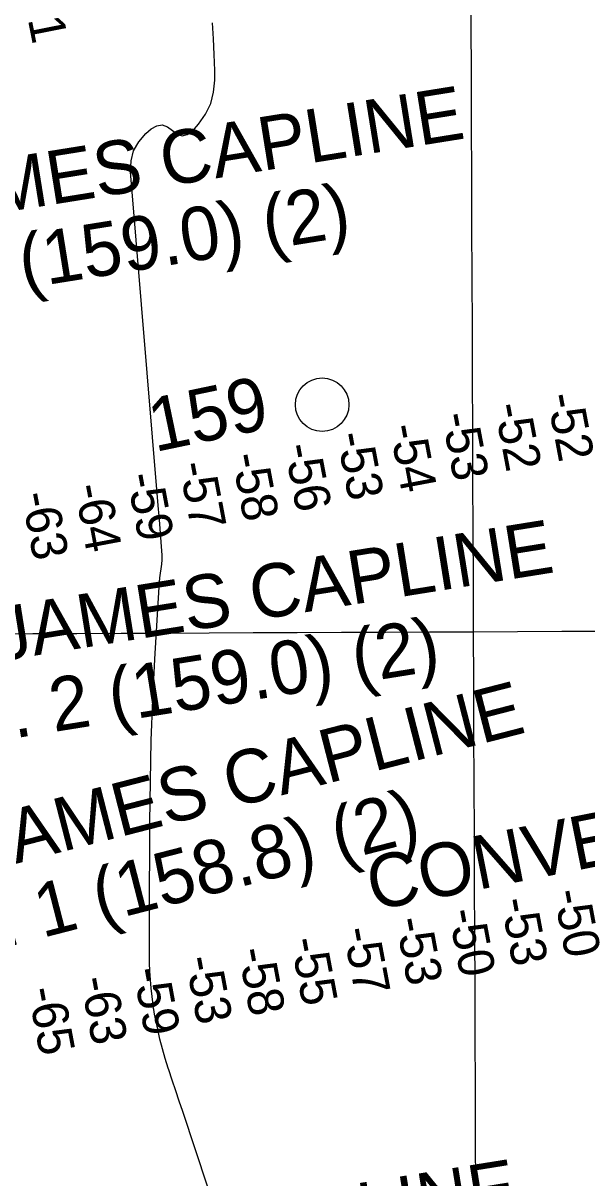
# Model space of a CAD drawing. Extents: x 3419139 to 3457078, y 540382 to 565875.
# Drawn here: x 3438230 to 3439284, y 550877 to 553037 of the extents above; entities that cross this region are included whole.
import ezdxf

# ---------------------------------------------------------------- set-up
doc = ezdxf.new("R2010")
doc.units = 0
for name, color, linetype in [('V-CHAN-NAID', 7, 'Continuous'), ('V-GRID-MAJR', 7, 'Continuous'), ('V-RIVR-IDEN', 7, 'Continuous'), ('V-RIVR-MILE', 7, 'Continuous'), ('V-RIVR-RANG', 7, 'Continuous'), ('V-TOPO-GNAM-IDEN', 7, 'Continuous'), ('V-TOPO-MINR', 7, 'Continuous')]:
    doc.layers.add(name, color=color, linetype=linetype)

msp = doc.modelspace()

# ---------------------------------------------------------------- linework, layer by layer
at = {"layer": 'V-GRID-MAJR'}
for points in [[(3439098.8, 545841.1), (3439072.3, 551898.7), (3439045.9, 557959.6), (3439019.4, 564020.6), (3439019.4, 564024.1)], [(3423248.5, 551833.1), (3428523.1, 551854.2), (3433797.7, 551876), (3439072.3, 551898.7), (3444346.9, 551922.1), (3449621.5, 551946.2), (3454896.1, 551971.2)]]:
    msp.add_spline(points, degree=3, dxfattribs=at)
at = {"layer": 'V-RIVR-MILE'}
msp.add_circle((3438789.1, 552323.2), 50, dxfattribs=at)
at = {"layer": 'V-TOPO-MINR'}
msp.add_lwpolyline([(3438575.5, 550860), (3438528.4, 551001.1), (3438521.9, 551020.6), (3438515.4, 551040.2), (3438508.9, 551059.7), (3438502.4, 551079.2), (3438501.4, 551082.4), (3438495.7, 551100.4), (3438490.5, 551118.5), (3438485.8, 551136.8), (3438481.6, 551155.2), (3438475.6, 551183.2), (3438474.7, 551187.7), (3438474, 551192.2), (3438473.3, 551196.6), (3438472.8, 551201.1), (3438469.5, 551232), (3438468.1, 551247.9), (3438467.1, 551263.8), (3438466.5, 551279.7), (3438466.3, 551295.7), (3438466.3, 551311.7), (3438466.4, 551327.6), (3438466.4, 551343.6), (3438466.5, 551359.6), (3438467, 551542.8), (3438467.9, 551619.1), (3438469.6, 551695.2), (3438472.6, 551771.4), (3438476.4, 551847.5), (3438484.2, 551982.8), (3438484.9, 551991.3), (3438485.7, 551999.7), (3438486.8, 552008.1), (3438488, 552016.4), (3438489.1, 552024.8), (3438489.8, 552033.2), (3438489.8, 552041.6), (3438489.5, 552050), (3438484.9, 552108.1), (3438484.3, 552114.7), (3438483.8, 552121.4), (3438483.2, 552128), (3438482.7, 552134.6), (3438430.7, 552758.8), (3438431.9, 552779), (3438436.5, 552797.9), (3438446.1, 552814.8), (3438459.1, 552830.4), (3438469.1, 552839.4), (3438479.7, 552844.6), (3438489.9, 552846.3), (3438499.6, 552842.8), (3438509, 552835.7), (3438518.2, 552829.3), (3438527.4, 552826.3), (3438536.9, 552828.7), (3438546.4, 552834.6), (3438557.9, 552847.8), (3438570.8, 552866.4), (3438580.7, 552886.2), (3438586, 552907.7), (3438588.3, 552930.2), (3438588.1, 552948.4), (3438587.4, 552978), (3438586.1, 553007.6), (3438583.8, 553037.1)], dxfattribs=at)

# ---------------------------------------------------------------- texts
at = {"layer": 'V-CHAN-NAID'}
for s, rotation, p in [('ST JAMES CAPLINE', 9.1127, (3437812, 552621.5)), ('NO. 2 (159.0) (2)', 9.1127, (3437848.7, 552478.9)), ('ST JAMES CAPLINE', 9.1127, (3437979.1, 551810.1)), ('NO. 2 (159.0) (2)', 9.1127, (3438015.8, 551667.5)), ('ST JAMES CAPLINE', 14.4384, (3437949.8, 551395.9)), ('NO. 1 (158.8) (2)', 14.4384, (3437999.6, 551257.3)), ('ST JAMES CAPLINE', 9.1127, (3437911, 550614.3))]:
    msp.add_text(s, height=100, rotation=rotation, dxfattribs=at).set_placement(p)
at = {"layer": 'V-RIVR-IDEN'}
msp.add_text('159', height=100, rotation=11.8277, dxfattribs=at).set_placement((3438476, 552234.4))
at = {"layer": 'V-RIVR-RANG'}
for s, rotation, p in [('-61', 281.16, (3438223.1, 553122.5)), ('-52', 280.6887, (3439208.9, 552340.4)), ('-53', 280.6887, (3439012.2, 552304.3)), ('-52', 280.6887, (3439110.6, 552322.1)), ('-54', 280.6887, (3438914.5, 552282.7)), ('-53', 280.6887, (3438815.6, 552267.7)), ('-56', 280.6887, (3438717.9, 552246.3)), ('-58', 280.6887, (3438619.5, 552228.5)), ('-57', 280.6887, (3438520.8, 552212.3)), ('-59', 280.6887, (3438423, 552191.2)), ('-63', 280.6887, (3438226.1, 552155.8)), ('-64', 280.6887, (3438325.1, 552170.8)), ('-53', 280.6027, (3439122.7, 551396.9)), ('-50', 280.6027, (3439221.5, 551412.7)), ('-50', 280.6027, (3439024.8, 551376.4)), ('-53', 280.6027, (3438926, 551360.6)), ('-57', 280.6027, (3438827.8, 551341.9)), ('-55', 280.6027, (3438729.6, 551322.7)), ('-58', 280.6027, (3438631.5, 551303.5)), ('-53', 280.6027, (3438532.7, 551287.9)), ('-63', 280.6027, (3438336.4, 551249.6)), ('-59', 280.6027, (3438434.9, 551266.4)), ('-65', 280.6027, (3438238.3, 551229.8))]:
    msp.add_text(s, height=67, rotation=rotation, dxfattribs=at).set_placement(p)
at = {"layer": 'V-TOPO-GNAM-IDEN'}
msp.add_text('CONVENT LDG.', height=100, rotation=11.1762, dxfattribs=at).set_placement((3438883.7, 551376.8))

doc.saveas('drawing.dxf')
